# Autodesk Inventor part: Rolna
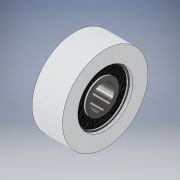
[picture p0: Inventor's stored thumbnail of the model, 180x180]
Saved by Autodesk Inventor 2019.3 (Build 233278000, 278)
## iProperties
Created: 2019-01
Part Number: Rolna
Material: Ocel, uhlík
Document SubType Name: Modeling
Designer: B-hon
Density: 7.85 g/cm^3
Appearance: Bílý
Author: B-hon
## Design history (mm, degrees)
sketch "Náčrt1"
  geometry: L1 (-6.584, 0)-(13.059, 0) reference; L2 (-4.298, 14)-(5.702, 14); L3 (5.702, 14)-(5.702, 9); L4 (5.702, 9)-(-4.298, 9); L5 (-4.298, 9)-(-4.298, 14); L6 (-3.298, 9)-(4.702, 9); L7 (4.702, 9)-(4.702, 4); L8 (4.702, 4)-(-3.298, 4); L9 (-3.298, 4)-(-3.298, 9); 1 further point
  constraints: 18 end point, 4 horizontal, 4 parallel, 2 perpendicular, 1 point on line
  dimensions: "d0" = 10 distance of L2.start L2.end; "d1" = 28 diameter of L2 L1; "d2" = 8 diameter of L8 L1; "d3" = 8 distance of L7.end L8.end; "d4" = 1 distance between parallel lines of L5 L9; "d5" = 18 diameter of L4 L1
revolve "Rotace1" sketch "Náčrt1" stored, may be unused: angle "d6" = 90 deg
sketch "Náčrt2"
  geometry: C1 r 5.5 at (0, 0); C2 r 8.5 at (0, 0); 1 further point
  constraints: 2 centre point, 2 coincident
  dimensions: "d7" = 17 diameter of C2; "d8" = 11 diameter of C1
extrude "Vysunutí1" cut sketch "Náčrt2" distance "d9" = 0.5; taper "d10" = 0 deg
sketch "Náčrt3"
  geometry: C1 r 5.5 at (0, 0); C2 r 8.5 at (0, 0); 1 further point
  constraints: 2 centre point, 2 coincident
  dimensions: "d11" = 11 diameter of C1; "d12" = 17 diameter of C2
extrude "Vysunutí2" cut sketch "Náčrt3" distance "d13" = 0.5; taper "d14" = 0 deg
node "Těleso1"
